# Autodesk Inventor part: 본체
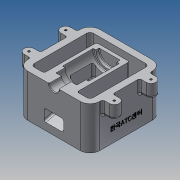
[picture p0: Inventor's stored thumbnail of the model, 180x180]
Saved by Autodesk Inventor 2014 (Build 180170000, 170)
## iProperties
Created: 2018-01
Part Number: 본체
Material: 알루미늄 6061
Document SubType Name: Modeling
Designer: 601-26
Density: 2.71 g/cm^3
Appearance: 알루미늄 - 평지
Mass: 998.502 g
Surface Area: 835.098 cm^2
Volume: 368.451 cm^3
Author: 601-26
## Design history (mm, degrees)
sketch "스케치1"
  geometry: L1 (55, -55)-(-55, -55); L2 (-55, -55)-(-55, 55); L3 (-55, 55)-(55, 55); L4 (55, 55)-(55, -55); L5 (55, -55)-(-55, 55); L6 (-55, -55)-(55, 55); 1 further point
  constraints: 12 end point, 2 midpoint, 2 parallel, 1 horizontal, 1 perpendicular
  dimensions: "d0" = 110 distance of L1.start L1.end; "d1" = 110 distance of L3.end L1.start
extrude "돌출1" new body sketch "스케치1" distance "d2" = 65; taper "d3" = 0 deg
sketch "스케치2"
  geometry: L1 (-55, -55)-(55, -55) reference; L2 (55, -55)-(55, 55) reference; L3 (55, 55)-(-55, 55) reference; L4 (-55, 55)-(-55, -55) reference; L5 (-45, 55)-(-45, 45); L6 (-55, 45)-(-45, 45); L7 (-55, 0)-(55, 0); L8 (-55, 25)-(-45, 25); L9 (-55, -25)-(-45, -25); L10 (45, 45)-(55, 45); L11 (-55, -45)-(-45, -45); L12 (45, -45)-(55, -45); L13 (45, 25)-(55, 25); L14 (45, -25)-(55, -25); L15 (-45, 25)-(35, 25); L16 (-45, 45)-(45, 45); L17 (-45, -25)-(35, -25); L18 (-45, -45)-(45, -45); L19 (55, 45)-(55, -45); L20 (-45, 45)-(-45, 25); L21 (-45, -45)-(-45, -55); L22 (-45, -25)-(-45, -45); L23 (-45, 25)-(-45, -25); L24 (35, 55)-(35, 45); L25 (35, 45)-(35, 25); L26 (35, -45)-(35, -55); L27 (35, 25)-(45, 25); L28 (35, -25)-(45, -25); L29 (35, 25)-(35, -25); L30 (35, -25)-(35, -45); L31 (45, 45)-(45, -45); 1 further point
  constraints: 54 end point, 16 perpendicular, 14 point on line, 9 parallel, 2 midpoint, 1 collinear, 1 other
  dimensions: "d4" = 10 distance between parallel lines of L4 L5; "d5" = 10 distance between parallel lines of L6 L3; "d6" = 50 distance between parallel lines of L9 L8; "d8" = 10 distance between parallel lines of L1 L11; "d9" = 20 distance between parallel lines of L19 L24; "d10" = 10 distance between parallel lines of L2 L31
extrude "돌출2" cut sketch "스케치2" distance "d11" = 110; taper "d12" = 0 deg
sketch "스케치4"
  geometry: L1 (-45, -25)-(35, -25) reference; L2 (35, -25)-(35, 25) reference; L3 (-55, 55)-(-55, -55) reference; L4 (35, 0)-(-55, 0); L5 (30, 0)-(30, -16); L6 (25, 0)-(25, -20); L7 (35, -20)-(25, -20); L8 (-22, 0)-(-22, -16); L9 (35, -16)-(30, -16); L10 (-36, -20)-(-36, -16); L11 (-55, -7.5)-(-36, -7.5); L12 (-36, -16)-(-55, -16); L13 (-36, -16)-(-36, 0); L14 (-22, -16)-(-22, -20); L15 (-22, -20)-(-55, -20); L16 (25, -16)-(-22, -16); L17 (-22, -16)-(-36, -16); L18 (25, -20)-(-22, -20); L19 (30, -16)-(30, -20); L20 (30, -16)-(25, -16); 1 further point
  constraints: 34 end point, 14 perpendicular, 14 point on line, 4 parallel, 3 midpoint
  dimensions: "d13" = 5 distance between parallel lines of L2 L5; "d14" = 5 distance between parallel lines of L6 L5; "d15" = 40 diameter of L7 L4; "d16" = 47 distance between parallel lines of L6 L8; "d17" = 32 diameter of L9 L4; "d18" = 14 distance between parallel lines of L8 L10; "d19" = 15 diameter of L11 L4
revolve "회전1" sketch "스케치4" stored, may be unused: angle "d20" = 90 deg
sketch "스케치8"
  geometry: L1 (80, -65)-(0, -65) reference; L2 (0, 0)-(80, 0) reference; L3 (0, 0)-(0, -65) reference; L4 (-10, -65)-(-10, 0) reference; L5 (-10, -35)-(90.247, -35); L6 (80, 0)-(80, -65); L7 (-10, -65)-(100, -65) reference; L8 (100, -65)-(100, 0) reference; L9 (80, 0)-(80, -65) reference; L10 (80, -35)-(0, -56.436); 1 further point
  constraints: 6 end point, 6 point on line, 2 perpendicular
  dimensions: "d44" = 30 distance between parallel lines of L1 L5; "d45" = 20 distance between parallel lines of L8 L6; "d46" = 105 deg angle of L3 L10
extrude "돌출4" cut sketch "스케치8" stored distance "d47" = 30; taper "d48" = 0 deg
sketch "스케치10"
  geometry: L1 (-25, 65)-(22, 65) reference; L2 (-25, 65)-(-25, 65) reference; L3 (22, 65)-(-25, 65) reference; L4 (22, 65)-(22, 65) reference; L5 (-35, 30)-(45, 8.564) reference; L6 (45, 65)-(45, 8.564) reference; L7 (-35, 65)-(45, 65) reference; L8 (-35, 65)-(-35, 30) reference; L9 (55, 11.061)-(-20, 31.157); L10 (55, 0)-(55, 65) reference; L11 (55, 29.061)-(17, 39.243); L12 (22, 45)-(-25, 45) reference; L13 (17, 54.243)-(-20, 54.243); L14 (17, 54.243)-(17, 39.243); L15 (-20, 54.243)-(-20, 31.157); 3 further points
  constraints: 10 end point, 2 midpoint, 2 parallel, 2 point on line, 1 perpendicular, 1 vertical alignment
  dimensions: "d55" = 5 distance between parallel lines of L5 L9; "d56" = 18 distance of L9.start L11.start; "d57" = 75 deg angle of L10 L11; "d58" = 105 deg angle of L10 L9 (derived); "d59" = 37 distance of L13.start L13.end; "d60" = 15 distance of L13.start L11.end
extrude "돌출5" cut sketch "스케치10" stored distance "d61" = 30; taper "d62" = 0 deg
sketch "스케치11"
  geometry: L1 (55, 55)-(-55, 55) reference; L2 (-55, 55)-(-55, 7.5) reference; L3 (35, 25)-(-45, 25) reference; L4 (55, 65)-(-55, 65); L5 (-28, 55)-(-28, 75); L6 (-20.5, 65)-(-20.5, 55); L7 (-35.5, 65)-(-35.5, 55); L8 (-55, 55)-(55, 55) reference; L9 (-35.5, 55)-(-20.5, 55); A1 r 7.5 centre (-28, 65) between (-20.5, 65) and (-35.5, 65); 1 further point
  constraints: 10 end point, 6 point on line, 3 perpendicular, 2 point on circle, 2 tangent, 1 centre point, 1 collinear, 1 midpoint, 1 parallel
  dimensions: "d66" = 10 distance between parallel lines of L1 L4; "d67" = 27 distance between parallel lines of L2 L5; "d68" = 15 diameter of A1
extrude "돌출6" join sketch "스케치11" distance "d69" = 20; taper "d70" = 0 deg
sketch "스케치12"
  geometry: A1 r 7.5 centre (-28, 65) between (-20.5, 65) and (-35.5, 65) reference; 2 further points
  constraints: 1 coincident
hole "구멍1" sketch "스케치12" at (-28, 65) diameter "d71" = 3.242; stored, may be unused: countersink angle "d75" = 82 deg, drill point angle "d77" = 118 deg; dims "d72" = 9, "d73" = 3.023, "d74" = 2, "d76" = 11
fillet "모깎기1" dims "d78" = 15
sketch "스케치13"
  geometry: L1 (-34.5, 0)-(-34.5, -65) reference; 2 further points
  constraints: 1 other
  dimensions: "d79" = 20 distance of point (20.5, -65) point (20.5, -45); "d80" = 55 distance from line of L1 point (20.5, -45)
extrude "돌출7" join sketch "스케치13" distance "d81" = 0.5; taper "d82" = 0 deg
fillet "모깎기2" dims "d83" = 1
fillet "모깎기3" dims "d84" = 3
fillet "모깎기4" dims "d85" = 3
fillet "모깎기5" dims "d86" = 3
fillet "모깎기6" dims "d87" = 3
fillet "모깎기7" dims "d88" = 3
chamfer "모따기1" distance "d89" = 1; stored, may be unused: second distance "d90" = 2, angle "d91" = 45 deg
fillet "모깎기9" dims "d93" = 5
fillet "모깎기10" dims "d94" = 3
node "솔리드1"
mirror "대칭1"
mirror "대칭2"
mirror "대칭3"
mirror "대칭4"
node "투영된 루프11"
node "투영된 루프12"
